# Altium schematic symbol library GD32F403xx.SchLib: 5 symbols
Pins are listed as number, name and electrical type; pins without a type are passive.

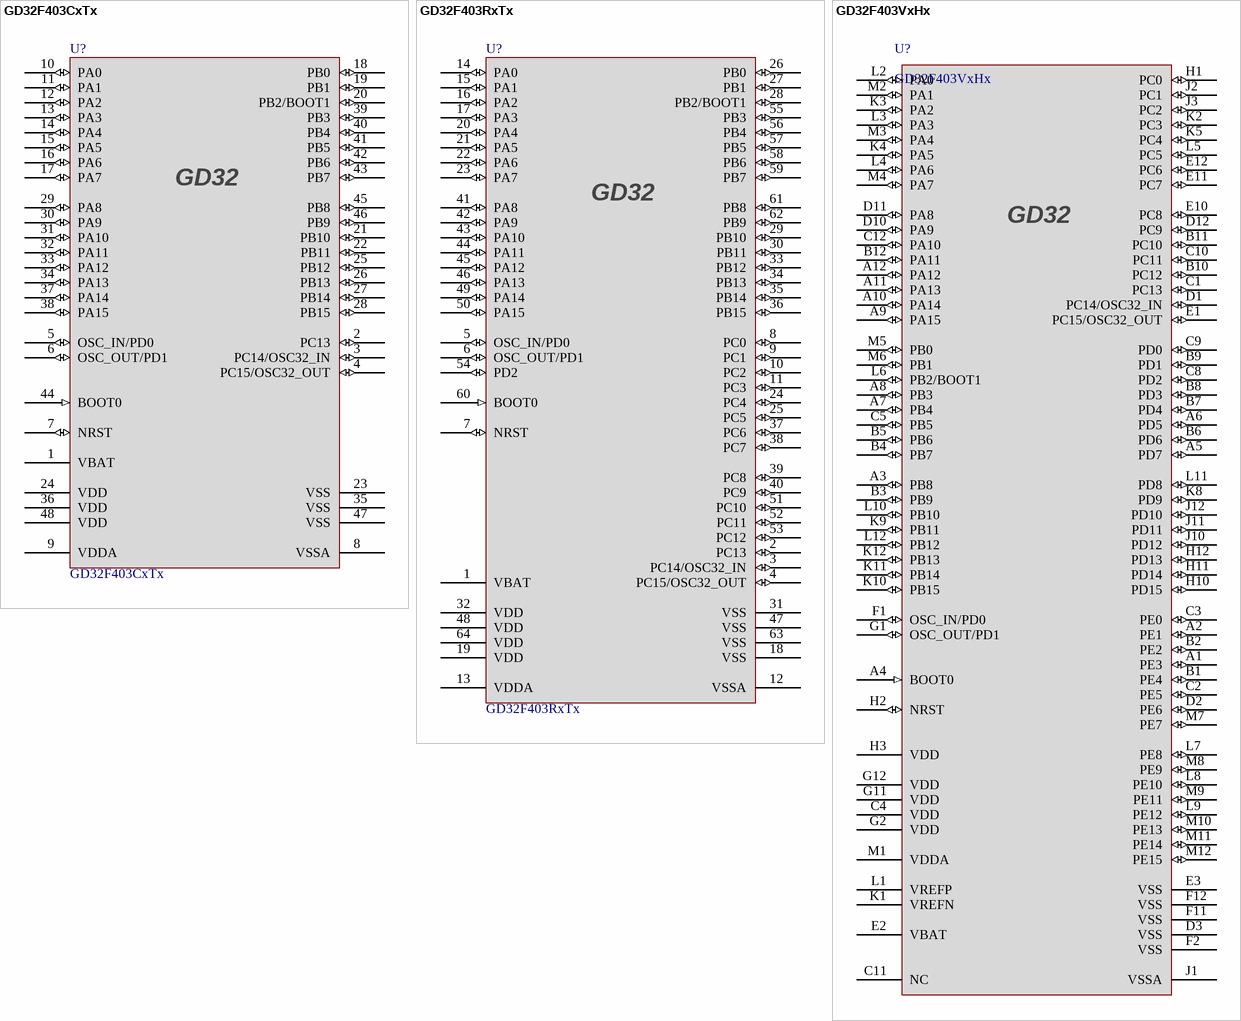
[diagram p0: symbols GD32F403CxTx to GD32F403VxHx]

## GD32F403CxTx
designator U?
footprint LQFP48_7x7x1.6
pins: 1 VBAT (power), 2 PC13 (io), 3 PC14/OSC32_IN (io), 4 PC15/OSC32_OUT (io), 5 OSC_IN/PD0 (io), 6 OSC_OUT/PD1 (io), 7 NRST (io), 8 VSSA (power), 9 VDDA (power), 10 PA0 (io), 11 PA1 (io), 12 PA2 (io), 13 PA3 (io), 14 PA4 (io), 15 PA5 (io), 16 PA6 (io), 17 PA7 (io), 18 PB0 (io), 19 PB1 (io), 20 PB2/BOOT1 (io), 21 PB10 (io), 22 PB11 (io), 23 VSS (power), 24 VDD (power), 25 PB12 (io), 26 PB13 (io), 27 PB14 (io), 28 PB15 (io), 29 PA8 (io), 30 PA9 (io), 31 PA10 (io), 32 PA11 (io), 33 PA12 (io), 34 PA13 (io), 35 VSS (power), 36 VDD (power), 37 PA14 (io), 38 PA15 (io), 39 PB3 (io), 40 PB4 (io), 41 PB5 (io), 42 PB6 (io), 43 PB7 (io), 44 BOOT0 (in), 45 PB8 (io), 46 PB9 (io), 47 VSS (power), 48 VDD (power)
2 alternate drawings of the same symbol

## GD32F403RxTx
designator U?
footprint LQPF64_10x10x1.6
pins: 1 VBAT (power), 2 PC13 (io), 3 PC14/OSC32_IN (io), 4 PC15/OSC32_OUT (io), 5 OSC_IN/PD0 (io), 6 OSC_OUT/PD1 (io), 7 NRST (io), 8 PC0 (io), 9 PC1 (io), 10 PC2 (io), 11 PC3 (io), 12 VSSA (power), 13 VDDA (power), 14 PA0 (io), 15 PA1 (io), 16 PA2 (io), 17 PA3 (io), 18 VSS (power), 19 VDD (power), 20 PA4 (io), 21 PA5 (io), 22 PA6 (io), 23 PA7 (io), 24 PC4 (io), 25 PC5 (io), 26 PB0 (io), 27 PB1 (io), 28 PB2/BOOT1 (io), 29 PB10 (io), 30 PB11 (io), 31 VSS (power), 32 VDD (power), 33 PB12 (io), 34 PB13 (io), 35 PB14 (io), 36 PB15 (io), 37 PC6 (io), 38 PC7 (io), 39 PC8 (io), 40 PC9 (io), 41 PA8 (io), 42 PA9 (io), 43 PA10 (io), 44 PA11 (io), 45 PA12 (io), 46 PA13 (io), 47 VSS (power), 48 VDD (power), 49 PA14 (io), 50 PA15 (io), 51 PC10 (io), 52 PC11 (io), 53 PC12 (io), 54 PD2 (io), 55 PB3 (io), 56 PB4 (io), 57 PB5 (io), 58 PB6 (io), 59 PB7 (io), 60 BOOT0 (in), 61 PB8 (io), 62 PB9 (io), 63 VSS (power), 64 VDD (power)
2 alternate drawings of the same symbol

## GD32F403VxHx
designator U?
footprint BGA100_7x7X0.84
pins: A1 PE3 (io), A2 PE1 (io), A3 PB8 (io), A4 BOOT0 (in), A5 PD7 (io), A6 PD5 (io), A7 PB4 (io), A8 PB3 (io), A9 PA15 (io), A10 PA14 (io), A11 PA13 (io), A12 PA12 (io), B1 PE4 (io), B2 PE2 (io), B3 PB9 (io), B4 PB7 (io), B5 PB6 (io), B6 PD6 (io), B7 PD4 (io), B8 PD3 (io), B9 PD1 (io), B10 PC12 (io), B11 PC10 (io), B12 PA11 (io), C1 PC13 (io), C2 PE5 (io), C3 PE0 (io), C4 VDD (power), C5 PB5 (io), C8 PD2 (io), C9 PD0 (io), C10 PC11 (io), C11 NC, C12 PA10 (io), D1 PC14/OSC32_IN (io), D2 PE6 (io), D3 VSS (power), D10 PA9 (io), D11 PA8 (io), D12 PC9 (io), E1 PC15/OSC32_OUT (io), E2 VBAT (power), E3 VSS (power), E10 PC8 (io), E11 PC7 (io), E12 PC6 (io), F1 OSC_IN/PD0 (io), F2 VSS (power), F11 VSS (power), F12 VSS (power), G1 OSC_OUT/PD1 (io), G2 VDD (power), G11 VDD (power), G12 VDD (power), H1 PC0 (io), H2 NRST (io), H3 VDD (power), H10 PD15 (io), H11 PD14 (io), H12 PD13 (io), J1 VSSA (power), J2 PC1 (io), J3 PC2 (io), J10 PD12 (io), J11 PD11 (io), J12 PD10 (io), K1 VREFN (power), K2 PC3 (io), K3 PA2 (io), K4 PA5 (io), K5 PC4 (io), K8 PD9 (io), K9 PB11 (io), K10 PB15 (io), K11 PB14 (io), K12 PB13 (io), L1 VREFP (power), L2 PA0 (io), L3 PA3 (io), L4 PA6 (io), L5 PC5 (io), L6 PB2/BOOT1 (io), L7 PE8 (io), L8 PE10 (io), L9 PE12 (io), L10 PB10 (io), L11 PD8 (io), L12 PB12 (io), M1 VDDA (power), M2 PA1 (io), M3 PA4 (io), M4 PA7 (io), M5 PB0 (io), M6 PB1 (io), M7 PE7 (io), M8 PE9 (io), M9 PE11 (io), M10 PE13 (io), M11 PE14 (io), M12 PE15 (io)

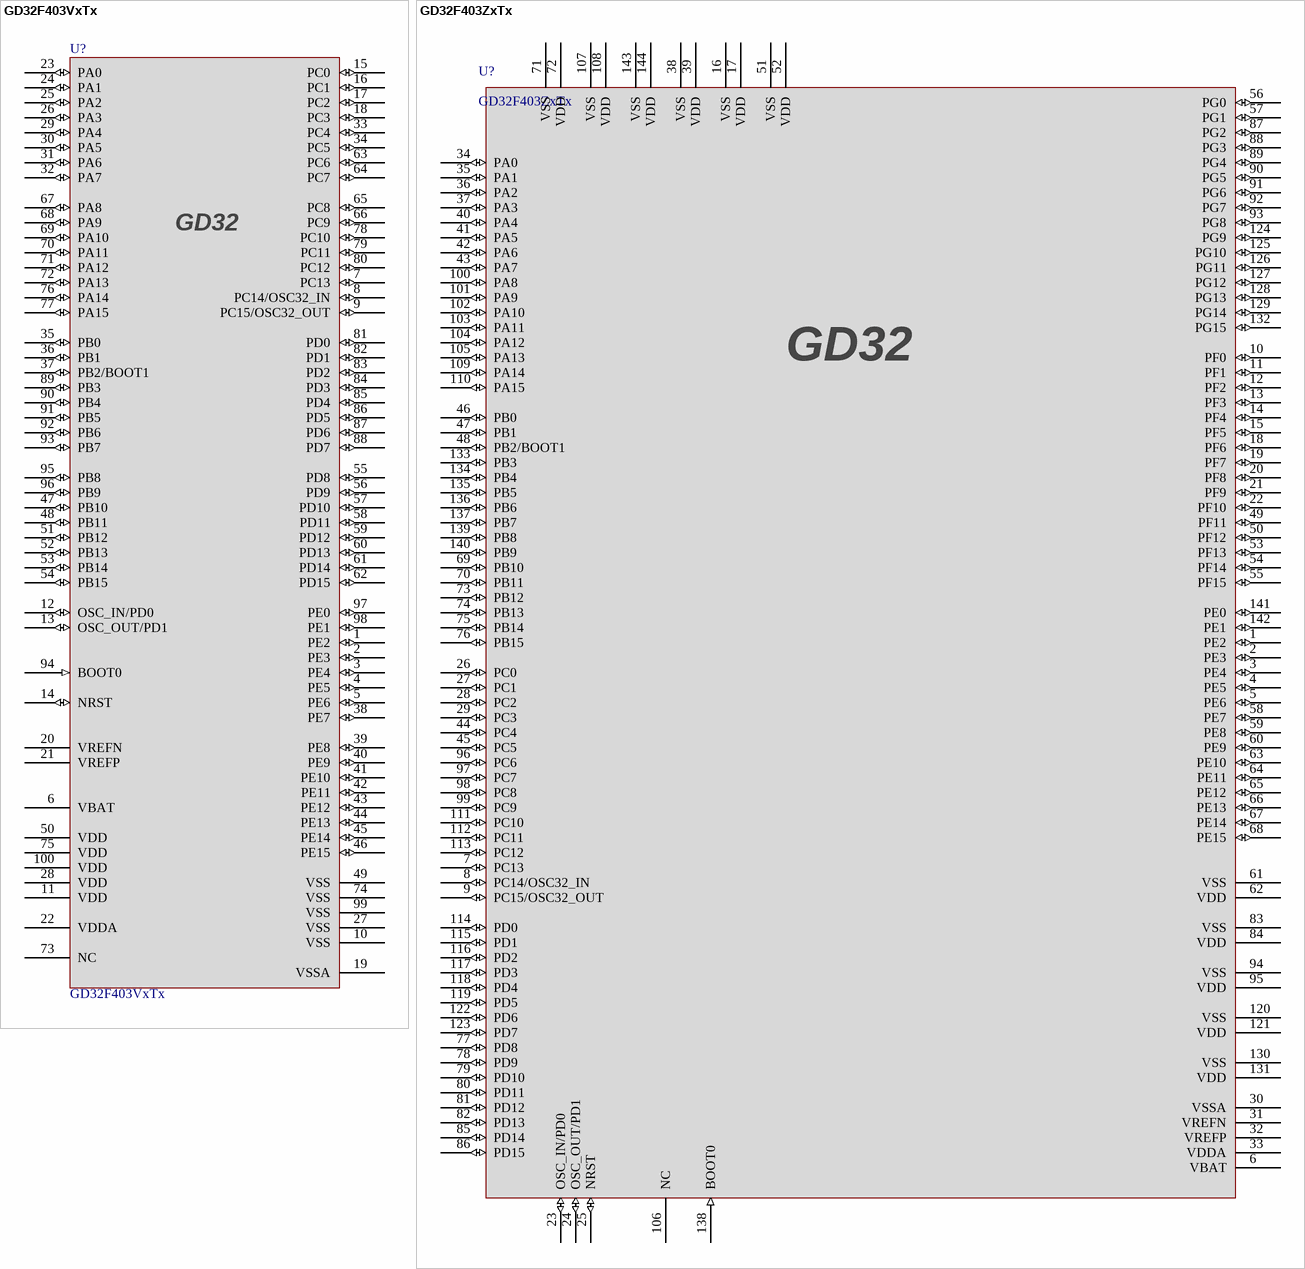
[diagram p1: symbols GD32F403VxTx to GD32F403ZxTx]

## GD32F403VxTx
designator U?
footprint LQFP100_14x14x1.6
pins: 1 PE2 (io), 2 PE3 (io), 3 PE4 (io), 4 PE5 (io), 5 PE6 (io), 6 VBAT (power), 7 PC13 (io), 8 PC14/OSC32_IN (io), 9 PC15/OSC32_OUT (io), 10 VSS (power), 11 VDD (power), 12 OSC_IN/PD0 (io), 13 OSC_OUT/PD1 (io), 14 NRST (io), 15 PC0 (io), 16 PC1 (io), 17 PC2 (io), 18 PC3 (io), 19 VSSA (power), 20 VREFN (power), 21 VREFP (power), 22 VDDA (power), 23 PA0 (io), 24 PA1 (io), 25 PA2 (io), 26 PA3 (io), 27 VSS (power), 28 VDD (power), 29 PA4 (io), 30 PA5 (io), 31 PA6 (io), 32 PA7 (io), 33 PC4 (io), 34 PC5 (io), 35 PB0 (io), 36 PB1 (io), 37 PB2/BOOT1 (io), 38 PE7 (io), 39 PE8 (io), 40 PE9 (io), 41 PE10 (io), 42 PE11 (io), 43 PE12 (io), 44 PE13 (io), 45 PE14 (io), 46 PE15 (io), 47 PB10 (io), 48 PB11 (io), 49 VSS (power), 50 VDD (power), 51 PB12 (io), 52 PB13 (io), 53 PB14 (io), 54 PB15 (io), 55 PD8 (io), 56 PD9 (io), 57 PD10 (io), 58 PD11 (io), 59 PD12 (io), 60 PD13 (io), 61 PD14 (io), 62 PD15 (io), 63 PC6 (io), 64 PC7 (io), 65 PC8 (io), 66 PC9 (io), 67 PA8 (io), 68 PA9 (io), 69 PA10 (io), 70 PA11 (io), 71 PA12 (io), 72 PA13 (io), 73 NC, 74 VSS (power), 75 VDD (power), 76 PA14 (io), 77 PA15 (io), 78 PC10 (io), 79 PC11 (io), 80 PC12 (io), 81 PD0 (io), 82 PD1 (io), 83 PD2 (io), 84 PD3 (io), 85 PD4 (io), 86 PD5 (io), 87 PD6 (io), 88 PD7 (io), 89 PB3 (io), 90 PB4 (io), 91 PB5 (io), 92 PB6 (io), 93 PB7 (io), 94 BOOT0 (in), 95 PB8 (io), 96 PB9 (io), 97 PE0 (io), 98 PE1 (io), 99 VSS (power), 100 VDD (power)
2 alternate drawings of the same symbol

## GD32F403ZxTx
designator U?
footprint LQFP144_20x20X1.6
pins: 1 PE2 (io), 2 PE3 (io), 3 PE4 (io), 4 PE5 (io), 5 PE6 (io), 6 VBAT (power), 7 PC13 (io), 8 PC14/OSC32_IN (io), 9 PC15/OSC32_OUT (io), 10 PF0 (io), 11 PF1 (io), 12 PF2 (io), 13 PF3 (io), 14 PF4 (io), 15 PF5 (io), 16 VSS (power), 17 VDD (power), 18 PF6 (io), 19 PF7 (io), 20 PF8 (io), 21 PF9 (io), 22 PF10 (io), 23 OSC_IN/PD0 (io), 24 OSC_OUT/PD1 (io), 25 NRST (io), 26 PC0 (io), 27 PC1 (io), 28 PC2 (io), 29 PC3 (io), 30 VSSA (power), 31 VREFN (power), 32 VREFP (power), 33 VDDA (power), 34 PA0 (io), 35 PA1 (io), 36 PA2 (io), 37 PA3  (io), 38 VSS (power), 39 VDD (power), 40 PA4 (io), 41 PA5 (io), 42 PA6 (io), 43 PA7 (io), 44 PC4 (io), 45 PC5 (io), 46 PB0 (io), 47 PB1 (io), 48 PB2/BOOT1 (io), 49 PF11 (io), 50 PF12 (io), 51 VSS (power), 52 VDD (power), 53 PF13 (io), 54 PF14 (io), 55 PF15 (io), 56 PG0 (io), 57 PG1 (io), 58 PE7 (io), 59 PE8 (io), 60 PE9 (io), 61 VSS (power), 62 VDD (power), 63 PE10 (io), 64 PE11 (io), 65 PE12 (io), 66 PE13 (io), 67 PE14 (io), 68 PE15 (io), 69 PB10 (io), 70 PB11 (io), 71 VSS (power), 72 VDD (power), 73 PB12 (io), 74 PB13 (io), 75 PB14 (io), 76 PB15 (io), 77 PD8 (io), 78 PD9 (io), 79 PD10 (io), 80 PD11 (io), 81 PD12 (io), 82 PD13 (io), 83 VSS (power), 84 VDD (power), 85 PD14 (io), 86 PD15 (io), 87 PG2 (io), 88 PG3 (io), 89 PG4 (io), 90 PG5 (io), 91 PG6 (io), 92 PG7 (io), 93 PG8 (io), 94 VSS (power), 95 VDD (power), 96 PC6 (io), 97 PC7 (io), 98 PC8 (io), 99 PC9 (io), 100 PA8 (io), 101 PA9 (io), 102 PA10 (io), 103 PA11 (io), 104 PA12 (io), 105 PA13 (io), 106 NC, 107 VSS (power), 108 VDD (power), 109 PA14 (io), 110 PA15 (io), 111 PC10 (io), 112 PC11 (io), 113 PC12 (io), 114 PD0 (io), 115 PD1 (io), 116 PD2 (io), 117 PD3 (io), 118 PD4 (io), 119 PD5 (io), 120 VSS (power), 121 VDD (power), 122 PD6 (io), 123 PD7 (io), 124 PG9 (io), 125 PG10 (io), 126 PG11 (io), 127 PG12 (io), 128 PG13 (io), 129 PG14 (io), 130 VSS (power), 131 VDD (power), 132 PG15 (io), 133 PB3 (io), 134 PB4 (io), 135 PB5 (io), 136 PB6 (io), 137 PB7 (io), 138 BOOT0 (in), 139 PB8 (io), 140 PB9 (io), 141 PE0 (io), 142 PE1 (io), 143 VSS (power), 144 VDD (power)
